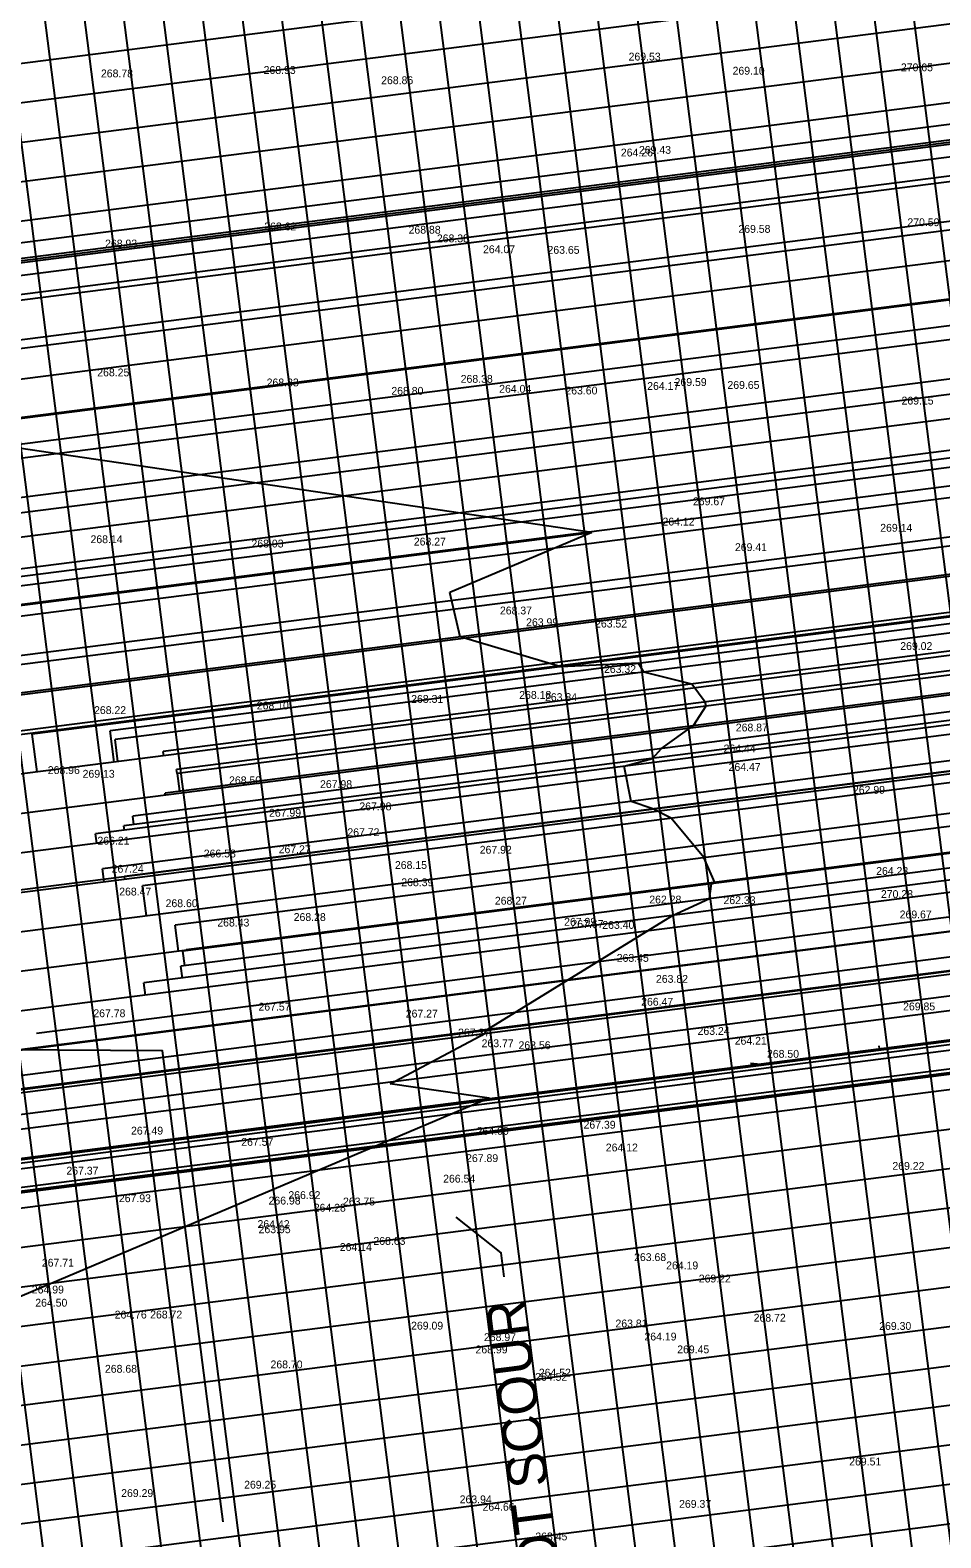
# Model space of a CAD drawing. Extents: x 2166991 to 2168450, y 842134 to 844444.
# Drawn here: x 2167870.5 to 2167986.8, y 843313.8 to 843506.3 of the extents above; entities that cross this region are included whole.
import ezdxf

# ---------------------------------------------------------------- set-up
doc = ezdxf.new("R2010")
doc.units = 0
for name, color, linetype in [('Exist Hydrographic Top of Bank', 7, 'Continuous'), ('Exist Plan Preparation Drainage Notes Label', 7, 'Continuous'), ('Prop Boundary Buffer Zone 1', 7, 'Continuous'), ('Prop Drainage Structure Pipe Collar Label', 7, 'Continuous'), ('Prop Drainage Structure Pipe CSP 18in Label', 7, 'Continuous'), ('Prop Drainage Structure Scour Hole Label', 7, 'Continuous'), ('Prop Erosion Rip Rap Class II', 7, 'Continuous'), ('Scratch_Level_3', 7, 'Continuous')]:
    doc.layers.add(name, color=color, linetype=linetype)

msp = doc.modelspace()

# ---------------------------------------------------------------- linework, layer by layer
at = {"layer": 'Exist Hydrographic Top of Bank'}
msp.add_lwpolyline([(2167895.15, 843315.83), (2167893.14, 843331.53), (2167887.44, 843375.99), (2167781.12, 843376.66)], dxfattribs=at)
at = {"layer": 'Exist Plan Preparation Drainage Notes Label'}
for p, q in [((2168033.15, 842802.17), (2167874.77, 844042.09)), ((2167983.55, 842795.83), (2167825.17, 844035.76)), ((2168069.66, 842832.03), (2167917.61, 844022.36)), ((2168054.78, 842830.13), (2167902.74, 844020.46)), ((2168059.74, 842830.77), (2167907.69, 844021.1)), ((2168064.7, 842831.4), (2167912.65, 844021.73)), ((2168039.9, 842828.23), (2167887.86, 844018.56)), ((2168044.86, 842828.87), (2167892.82, 844019.19)), ((2168049.82, 842829.5), (2167897.78, 844019.83)), ((2168025.02, 842826.33), (2167872.98, 844016.66)), ((2168034.94, 842827.6), (2167882.9, 844017.93)), ((2168010.14, 842824.43), (2167858.1, 844014.76)), ((2168015.1, 842825.06), (2167863.06, 844015.39)), ((2168020.06, 842825.7), (2167868.02, 844016.03)), ((2167995.26, 842822.53), (2167843.22, 844012.86)), ((2168000.22, 842823.16), (2167848.18, 844013.49)), ((2168005.18, 842823.8), (2167853.14, 844014.13)), ((2167985.34, 842821.26), (2167833.3, 844011.59)), ((2167990.3, 842821.9), (2167838.26, 844012.23)), ((2167965.5, 842818.73), (2167813.46, 844009.06)), ((2167970.46, 842819.36), (2167818.42, 844009.69)), ((2167975.42, 842820), (2167823.38, 844010.33)), ((2167950.62, 842816.83), (2167798.58, 844007.16)), ((2167955.58, 842817.46), (2167803.54, 844007.79)), ((2167960.54, 842818.1), (2167808.5, 844008.43)), ((2167935.74, 842814.93), (2167783.7, 844005.26)), ((2167940.7, 842815.56), (2167788.66, 844005.89)), ((2167945.66, 842816.2), (2167793.62, 844006.52)), ((2168140.94, 843536.74), (2167644.97, 843473.39)), ((2168141.58, 843531.78), (2167645.61, 843468.43)), ((2168142.21, 843526.83), (2167646.24, 843463.47)), ((2168142.84, 843521.87), (2167646.87, 843458.52)), ((2168143.48, 843516.91), (2167647.51, 843453.56)), ((2168144.11, 843511.95), (2167648.14, 843448.6)), ((2168144.74, 843506.99), (2167648.77, 843443.64)), ((2168145.38, 843502.03), (2167649.41, 843438.68)), ((2168146.01, 843497.07), (2167625.24, 843430.55)), ((2168146.64, 843492.11), (2167650.67, 843428.76)), ((2168147.28, 843487.15), (2167651.31, 843423.8)), ((2168147.91, 843482.19), (2167651.94, 843418.84)), ((2168148.54, 843477.23), (2167652.57, 843413.88)), ((2168149.18, 843472.27), (2167653.21, 843408.92)), ((2168149.81, 843467.31), (2167653.84, 843403.96)), ((2168150.44, 843462.35), (2167654.47, 843399)), ((2168151.08, 843457.39), (2167655.11, 843394.04)), ((2168151.71, 843452.43), (2167655.74, 843389.08)), ((2168152.35, 843447.47), (2167631.58, 843380.95)), ((2168152.98, 843442.51), (2167657.01, 843379.16)), ((2168153.61, 843437.55), (2167657.64, 843374.2)), ((2168154.25, 843432.59), (2167658.28, 843369.24)), ((2168154.88, 843427.63), (2167658.91, 843364.28)), ((2168155.51, 843422.67), (2167659.54, 843359.32)), ((2168156.15, 843417.71), (2167660.18, 843354.36)), ((2168156.78, 843412.75), (2167660.81, 843349.4)), ((2168157.41, 843407.79), (2167661.44, 843344.44)), ((2168158.05, 843402.83), (2167662.08, 843339.48)), ((2168158.68, 843397.87), (2167637.91, 843331.35)), ((2168159.31, 843392.91), (2167663.34, 843329.56)), ((2168159.95, 843387.95), (2167663.98, 843324.6)), ((2168160.58, 843382.99), (2167664.61, 843319.64)), ((2168161.21, 843378.03), (2167665.24, 843314.68)), ((2168161.85, 843373.07), (2167665.88, 843309.72)), ((2168162.48, 843368.11), (2167666.51, 843304.76)), ((2168163.11, 843363.15), (2167667.14, 843299.8)), ((2168163.75, 843358.2), (2167667.78, 843294.84)), ((2168164.38, 843353.24), (2167668.41, 843289.89)), ((2168165.02, 843348.28), (2167644.25, 843281.76)), ((2168165.65, 843343.32), (2167669.68, 843279.97)), ((2168166.28, 843338.36), (2167670.31, 843275.01))]:
    msp.add_line(p, q, dxfattribs=at)
at = {"layer": 'Prop Boundary Buffer Zone 1'}
for p, q in [((2168091.54, 843505.51), (2167796.91, 843467.87)), ((2168090.16, 843485.03), (2167799.4, 843447.89)), ((2168089.2, 843465.59), (2167801.33, 843428.82)), ((2168087.87, 843444.75), (2167804.17, 843408.52)), ((2168086.81, 843424.32), (2167806.08, 843388.46)), ((2168086.26, 843403.82), (2167808.5, 843368.34)), ((2168086.42, 843400.54), (2167809.11, 843365.12)), ((2168085.19, 843389.79), (2167809.7, 843354.6)), ((2168085.19, 843385.4), (2167810.15, 843350.27))]:
    msp.add_line(p, q, dxfattribs=at)
at = {"layer": 'Prop Drainage Structure Pipe Collar Label'}
for p, q in [((2167942.23, 843442.17), (2167832.09, 843458.36)), ((2167942.23, 843442.17), (2167924.1, 843434.51)), ((2167963.34, 843374.3), (2167962.46, 843374.35)), ((2167929.12, 843369.93), (2167916.47, 843371.79)), ((2167929.12, 843369.93), (2167826.58, 843326.57))]:
    msp.add_line(p, q, dxfattribs=at)
for points in [[(2167916.47, 843371.79), (2167928.57, 843378.18), (2167928.81, 843378.68), (2167952.5, 843393.27), (2167957.22, 843395.42), (2167957.48, 843397.32), (2167957.91, 843397.47), (2167956.5, 843400.65), (2167952.33, 843405.69), (2167950.01, 843406.87), (2167947.22, 843407.82), (2167946.34, 843412.32), (2167949.94, 843413.33), (2167951.09, 843414.57), (2167955.2, 843417.51), (2167956.8, 843420.02), (2167956.68, 843420.52), (2167954.98, 843422.82), (2167948.84, 843424.34), (2167948.19, 843425.47), (2167938.26, 843425.02), (2167925.43, 843428.83), (2167924.1, 843434.51)], [(2167978.91, 843376.29), (2167978.87, 843376.63)], [(2167915.33, 843361.79), (2167914.99, 843361.71)]]:
    msp.add_lwpolyline(points, dxfattribs=at)
at = {"layer": 'Prop Drainage Structure Pipe CSP 18in Label'}
for p, q in [((2167765.91, 843419.65), (2167942.23, 843442.17)), ((2167779.93, 843350.85), (2167929.19, 843369.92))]:
    msp.add_line(p, q, dxfattribs=at)
at = {"layer": 'Prop Drainage Structure Scour Hole Label'}
for p, q in [((2168088.64, 843507.14), (2167815.29, 843472.22)), ((2168088.67, 843504.62), (2167844.97, 843473.49)), ((2168088.99, 843503.04), (2167845.52, 843471.94)), ((2168088.56, 843500.54), (2167849.85, 843470.04)), ((2168087.31, 843493.51), (2167854.58, 843463.78)), ((2168086.48, 843481.16), (2167855.37, 843451.64)), ((2168085.73, 843472.3), (2167855.38, 843442.88)), ((2168086.66, 843460.73), (2167855.42, 843431.19)), ((2168086.56, 843449.42), (2167857.98, 843420.22)), ((2168086.26, 843443.93), (2167870.81, 843416.41)), ((2168085.95, 843443.06), (2167880.74, 843416.85)), ((2168086.24, 843441.89), (2167881.38, 843415.73)), ((2168085.76, 843439.53), (2167887.53, 843414.21)), ((2168085.72, 843437.01), (2167889.23, 843411.91)), ((2168086, 843436.52), (2167889.35, 843411.4)), ((2168085.66, 843434.17), (2167887.75, 843408.89)), ((2168085.67, 843431.76), (2167883.64, 843405.95)), ((2168085.72, 843430.12), (2167878.89, 843403.7)), ((2168085.01, 843430.58), (2167882.49, 843404.72)), ((2168085.22, 843425.45), (2167879.76, 843399.21)), ((2168085.6, 843424.18), (2167882.56, 843398.25)), ((2168085.36, 843422.68), (2167884.87, 843397.07)), ((2167871.43, 843411.59), (2167870.81, 843416.41)), ((2167881.25, 843412.84), (2167880.74, 843416.85)), ((2168085.27, 843417.09), (2167889.05, 843392.03)), ((2167881.74, 843412.91), (2167881.38, 843415.73)), ((2167887.6, 843413.65), (2167887.53, 843414.21)), ((2168085.04, 843413.62), (2167890.03, 843388.71)), ((2168084.94, 843413.7), (2167890.46, 843388.86)), ((2168084.37, 843410.11), (2167885.05, 843384.65)), ((2167889.3, 843411.39), (2167889.23, 843411.91)), ((2167889.64, 843409.13), (2167889.35, 843411.4)), ((2168084.85, 843411.72), (2167889.77, 843386.8)), ((2167887.78, 843408.64), (2167887.75, 843408.89)), ((2167882.56, 843404.17), (2167882.49, 843404.72)), ((2167883.78, 843404.88), (2167883.64, 843405.95)), ((2167879.04, 843402.48), (2167878.89, 843403.7)), ((2168083.92, 843398.49), (2167861.36, 843370.07)), ((2167879.97, 843397.56), (2167879.76, 843399.21)), ((2168083.92, 843398.03), (2167861.12, 843369.57)), ((2167882.6, 843397.89), (2167882.56, 843398.25)), ((2167885.37, 843393.21), (2167884.87, 843397.07)), ((2167889.47, 843388.69), (2167889.05, 843392.03)), ((2168082.84, 843388.87), (2167838.25, 843357.63)), ((2168083.55, 843389.39), (2167839.68, 843358.24)), ((2167890.47, 843388.77), (2167890.46, 843388.86)), ((2167890.26, 843386.87), (2167890.03, 843388.71)), ((2168083.95, 843385.46), (2167834.18, 843353.55)), ((2168082.98, 843385.82), (2167834.96, 843354.14)), ((2167889.96, 843385.28), (2167889.77, 843386.8)), ((2167885.25, 843383.11), (2167885.05, 843384.65))]:
    msp.add_line(p, q, dxfattribs=at)
at = {"layer": 'Prop Erosion Rip Rap Class II'}
msp.add_lwpolyline([(2167931.04, 843347.13), (2167930.65, 843350.18), (2167924.9, 843354.74)], dxfattribs=at)
at = {"layer": 'Scratch_Level_3'}
for p, q in [((2167815.39, 843428.51), (2168411.81, 843504.69)), ((2167861.89, 843424.37), (2168413.08, 843494.78)), ((2167871.33, 843378.22), (2168277.38, 843430.09)), ((2167817.84, 843361.31), (2168278.64, 843420.17))]:
    msp.add_line(p, q, dxfattribs=at)

# ---------------------------------------------------------------- texts
at = {"layer": 'Prop Erosion Rip Rap Class II'}
msp.add_text('OT SCOUR', height=5, rotation=97.279, dxfattribs=at).set_placement((2167938.1, 843309.47))
at = {"layer": 'Scratch_Level_3'}
for s, p in [('269.53', (2167946.91, 843502.44)), ('268.78', (2167879.57, 843500.29)), ('268.93', (2167900.33, 843500.73)), ('269.10', (2167960.18, 843500.64)), ('270.65', (2167981.66, 843501.07)), ('268.86', (2167915.33, 843499.42)), ('264.26', (2167945.92, 843490.19)), ('269.43', (2167948.23, 843490.53)), ('268.62', (2167900.41, 843480.75)), ('268.88', (2167918.83, 843480.33)), ('269.58', (2167960.92, 843480.44)), ('270.59', (2167982.49, 843481.29)), ('268.93', (2167880.1, 843478.57)), ('268.38', (2167922.44, 843479.23)), ('264.07', (2167928.33, 843477.84)), ('263.65', (2167936.56, 843477.76)), ('268.25', (2167879.1, 843462.11)), ('268.38', (2167925.48, 843461.29)), ('268.33', (2167900.72, 843460.83)), ('268.80', (2167916.63, 843459.76)), ('264.04', (2167930.39, 843460.02)), ('263.60', (2167938.84, 843459.8)), ('264.17', (2167949.28, 843460.38)), ('269.59', (2167952.78, 843460.88)), ('269.65', (2167959.52, 843460.51)), ('269.15', (2167981.74, 843458.51)), ('269.67', (2167955.12, 843445.65)), ('264.12', (2167951.23, 843443.06)), ('269.14', (2167979.02, 843442.27)), ('268.14', (2167878.24, 843440.81)), ('268.03', (2167898.78, 843440.26)), ('268.27', (2167919.5, 843440.51)), ('269.41', (2167960.48, 843439.8)), ('268.37', (2167930.49, 843431.71)), ('263.99', (2167933.83, 843430.21)), ('263.52', (2167942.63, 843430.04)), ('269.02', (2167981.58, 843427.17)), ('263.32', (2167943.77, 843424.23)), ('268.18', (2167932.95, 843420.93)), ('263.84', (2167936.24, 843420.65)), ('268.22', (2167878.69, 843418.99)), ('268.10', (2167899.46, 843419.58)), ('268.31', (2167919.16, 843420.42)), ('268.87', (2167960.59, 843416.77)), ('264.44', (2167959.03, 843414.09)), ('268.96', (2167872.78, 843411.33)), ('264.47', (2167959.67, 843411.73)), ('269.13', (2167877.23, 843410.86)), ('268.50', (2167895.92, 843410.03)), ('267.98', (2167907.53, 843409.54)), ('262.99', (2167975.54, 843408.81)), ('267.99', (2167901.02, 843405.88)), ('267.98', (2167912.55, 843406.7)), ('267.72', (2167911.02, 843403.4)), ('266.21', (2167879.12, 843402.32)), ('266.58', (2167892.69, 843400.68)), ('267.27', (2167902.25, 843401.22)), ('267.92', (2167927.91, 843401.16)), ('267.24', (2167880.94, 843398.73)), ('268.15', (2167917.09, 843399.21)), ('264.23', (2167978.5, 843398.45)), ('268.47', (2167881.9, 843395.82)), ('268.39', (2167917.9, 843397.01)), ('268.60', (2167887.82, 843394.33)), ('268.27', (2167929.84, 843394.65)), ('262.28', (2167949.55, 843394.8)), ('262.33', (2167959.02, 843394.72)), ('270.28', (2167979.11, 843395.5)), ('268.43', (2167894.42, 843391.86)), ('268.28', (2167904.17, 843392.57)), ('267.99', (2167938.68, 843391.96)), ('267.67', (2167939.61, 843391.68)), ('269.67', (2167981.5, 843392.9)), ('263.40', (2167943.55, 843391.56)), ('263.45', (2167945.39, 843387.35)), ('263.82', (2167950.4, 843384.67)), ('267.78', (2167878.6, 843380.28)), ('267.57', (2167899.67, 843381.12)), ('267.27', (2167918.47, 843380.24)), ('266.47', (2167948.51, 843381.75)), ('269.85', (2167981.94, 843381.15)), ('267.37', (2167925.14, 843377.82)), ('263.77', (2167928.15, 843376.45)), ('263.24', (2167955.71, 843378.02)), ('264.21', (2167960.45, 843376.77)), ('263.56', (2167932.86, 843376.2)), ('268.50', (2167964.57, 843375.1)), ('267.49', (2167883.41, 843365.29)), ('264.00', (2167927.53, 843365.26)), ('267.39', (2167941.16, 843366.05)), ('267.57', (2167897.48, 843363.86)), ('264.12', (2167944, 843363.14)), ('267.89', (2167926.17, 843361.78)), ('267.37', (2167875.16, 843360.18)), ('266.54', (2167923.24, 843359.16)), ('269.22', (2167980.57, 843360.79)), ('266.92', (2167903.49, 843357.06)), ('267.93', (2167881.86, 843356.66)), ('266.98', (2167900.96, 843356.36)), ('264.28', (2167906.73, 843355.45)), ('263.75', (2167910.46, 843356.24)), ('264.42', (2167899.55, 843353.36)), ('263.95', (2167899.69, 843352.7)), ('264.14', (2167910.05, 843350.43)), ('268.63', (2167914.34, 843351.21)), ('267.71', (2167872.03, 843348.43)), ('263.68', (2167947.61, 843349.14)), ('264.19', (2167951.7, 843348.08)), ('269.22', (2167955.86, 843346.41)), ('264.99', (2167870.75, 843345)), ('264.50', (2167871.19, 843343.32)), ('264.76', (2167881.32, 843341.8)), ('268.72', (2167885.85, 843341.81)), ('269.09', (2167919.15, 843340.39)), ('263.81', (2167945.23, 843340.67)), ('268.72', (2167962.87, 843341.4)), ('269.30', (2167978.89, 843340.35)), ('268.97', (2167928.45, 843338.92)), ('264.19', (2167948.93, 843339)), ('268.99', (2167927.37, 843337.35)), ('269.45', (2167953.11, 843337.36)), ('268.68', (2167880.08, 843334.88)), ('268.70', (2167901.21, 843335.44)), ('264.52', (2167935.45, 843334.39)), ('264.52', (2167934.98, 843333.85)), ('269.51', (2167975.06, 843323.04)), ('269.29', (2167882.15, 843319.01)), ('269.25', (2167897.84, 843320.08)), ('263.94', (2167925.35, 843318.21)), ('264.66', (2167928.27, 843317.26)), ('269.37', (2167953.35, 843317.63)), ('268.45', (2167935, 843313.47))]:
    msp.add_text(s, height=1, dxfattribs=at).set_placement(p)

doc.saveas('drawing.dxf')
